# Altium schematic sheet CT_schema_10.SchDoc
size 277 x 170 mm
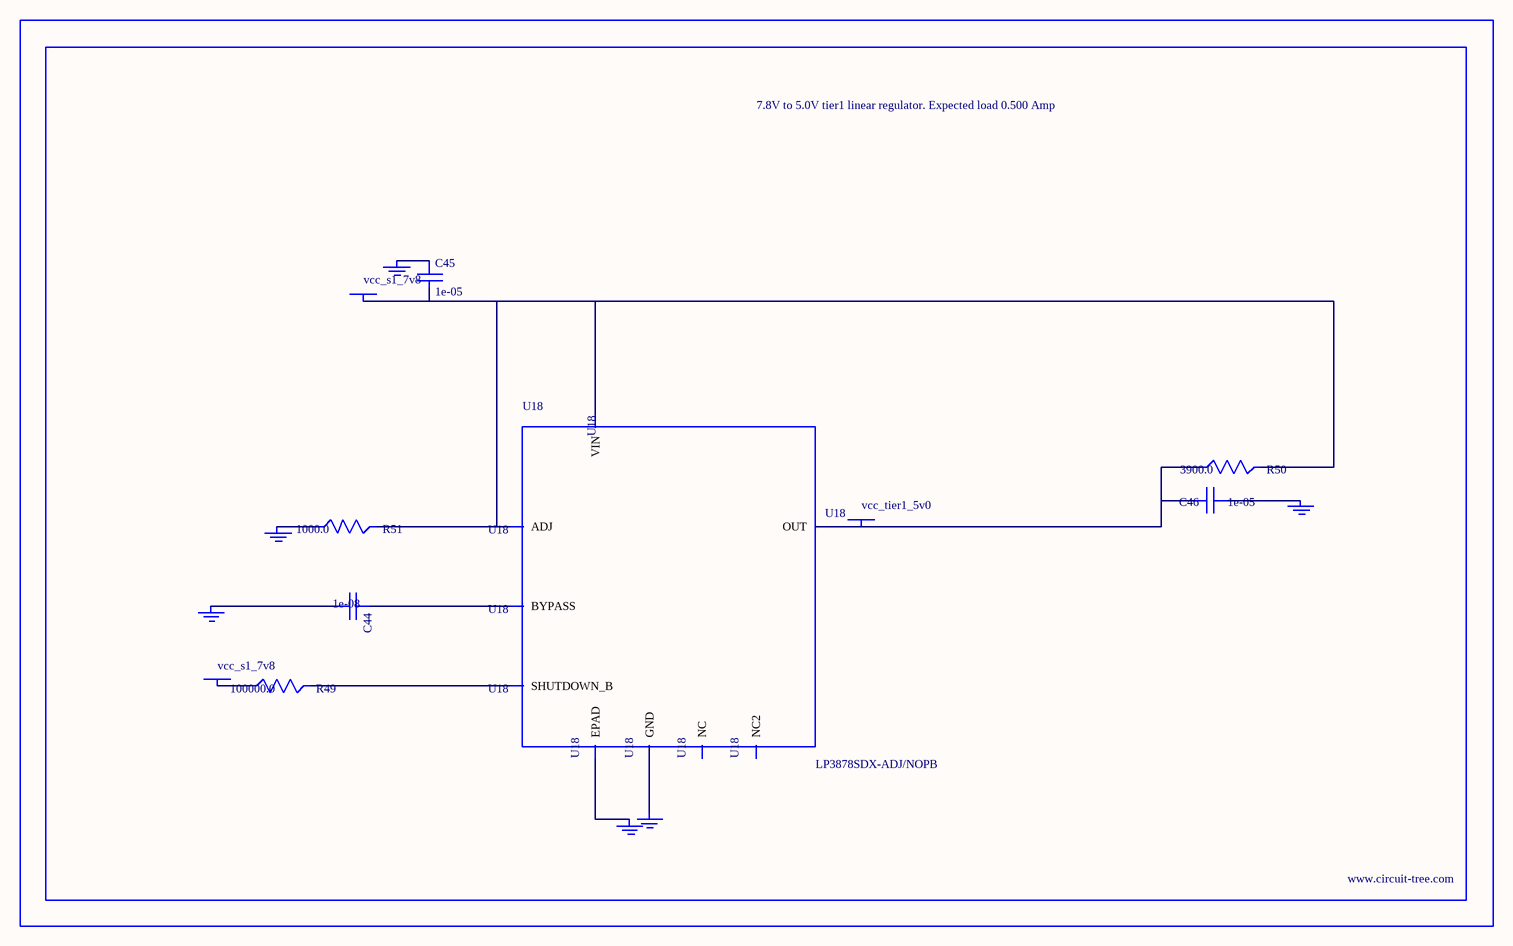
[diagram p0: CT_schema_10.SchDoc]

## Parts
BORDER9  (no value)
C44  1e-08  [C0402]
C45  1e-05  [C1206]
C46  1e-05  [C1210]
GND_INSTANCE_9_0  (no value)
GND_INSTANCE_9_1  (no value)
GND_INSTANCE_9_2  (no value)
GND_INSTANCE_9_3  (no value)
GND_INSTANCE_9_4  (no value)
GND_INSTANCE_9_5  (no value)
POWER_INSTANCE_9_0  vcc_s1_7v8
POWER_INSTANCE_9_1  vcc_s1_7v8
POWER_INSTANCE_9_2  vcc_tier1_5v0
R49  100000.0  [R0603]
R50  3900.0  [R0603]
R51  1000.0  [R0603]
U18  LP3878SDX-ADJ/NOPB  [WSON-8]

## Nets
NetC44_1: C44.1 U18.1(BYPASS)
NetC44_2: C44.2 GND_INSTANCE_9_0.0(GND)
NetC45_1: C45.1 GND_INSTANCE_9_1.0(GND)
NetC45_2: C45.2 POWER_INSTANCE_9_0.0(PWR) R50.2 R51.2 U18.4(VIN) U18.6(ADJ)
NetC46_1: C46.1 GND_INSTANCE_9_2.0(GND)
NetC46_2: C46.2 POWER_INSTANCE_9_2.0(PWR) R50.1 U18.5(OUT)
NetGND_INSTANCE_9_3_0: GND_INSTANCE_9_3.0(GND) R51.1
NetGND_INSTANCE_9_4_0: GND_INSTANCE_9_4.0(GND) U18.PAD(EPAD)
NetGND_INSTANCE_9_5_0: GND_INSTANCE_9_5.0(GND) U18.3(GND)
NetPOWER_INSTANCE_9_1_0: POWER_INSTANCE_9_1.0(PWR) R49.1
NetR49_2: R49.2 U18.8(SHUTDOWN_B)

Not connected (* = marked no-connect by the designer): U18 2(NC) 7(NC2)

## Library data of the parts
BORDER9 = BORDER_PAGE9
C44 = C0402C103K3RAC
C45 = C1206C106K3RACTU
C46 = GRM32DR61E106MA12L
GND_INSTANCE_9_0-GND_INSTANCE_9_5 = GND
POWER_INSTANCE_9_0-POWER_INSTANCE_9_2 = PWR
R49 = RC0603JR-07100KL
R50 = RC0603JR-073K9L
R51 = RC0603JR-071KL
